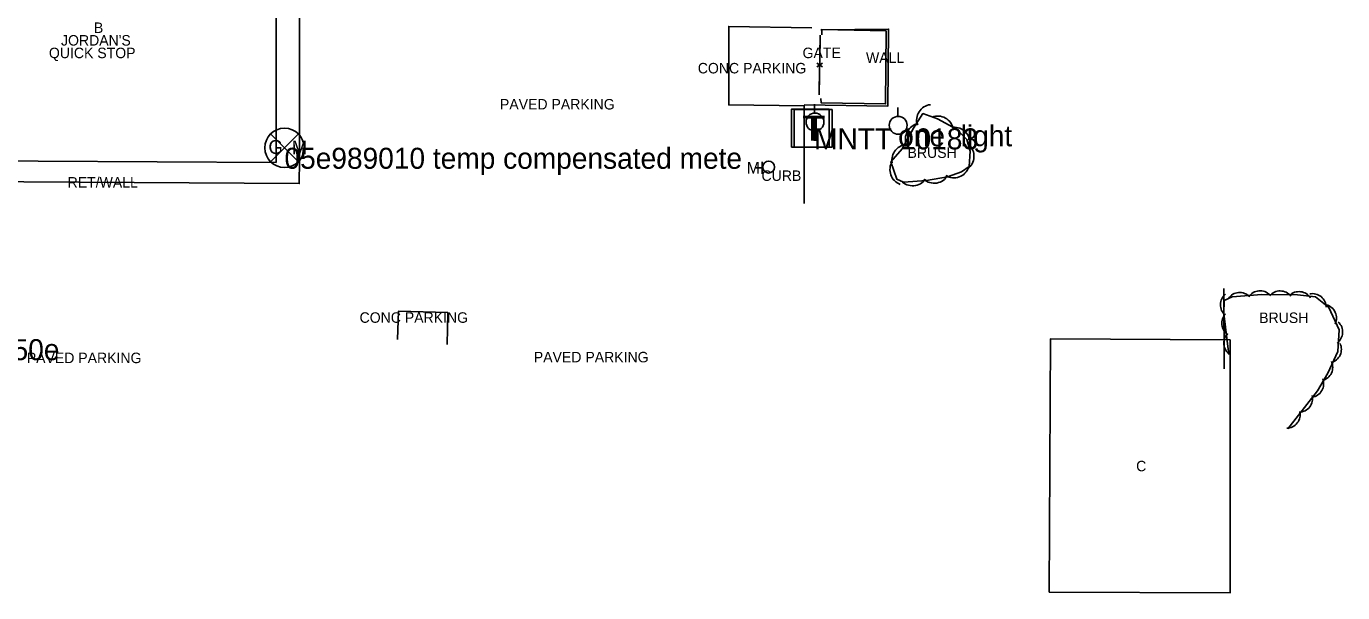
# Model space of a CAD drawing. Extents: x 1802180 to 1804859, y 572524 to 575172.
# Drawn here: x 1803724.4 to 1804037.7, y 573448 to 573582.9 of the extents above; entities that cross this region are included whole.
import ezdxf

# ---------------------------------------------------------------- set-up
doc = ezdxf.new("R2010")
doc.units = 0
for name, color, linetype in [('S_BUILDING', 7, 'Continuous'), ('S_BUILDING_ANNOT', 7, 'Continuous'), ('S_CURB_ANNOT', 7, 'Continuous'), ('S_FENCE', 7, 'Continuous'), ('S_GAS_UTILITIES', 7, 'Continuous'), ('S_GAS_UTILITIES_ANNOT', 7, 'Continuous'), ('S_GATE_ANNOT', 7, 'Continuous'), ('S_MANHOLE', 7, 'Continuous'), ('S_PARKING', 7, 'Continuous'), ('S_PARKING_ANNOT', 7, 'Continuous'), ('S_TELEPHONE_UTILITIES', 7, 'Continuous'), ('S_TELEPHONE_UTILITIES_ANNOT', 7, 'Continuous'), ('S_TREE', 7, 'Continuous'), ('S_TREE_ANNOT', 7, 'Continuous'), ('S_UTILITY_POLE', 7, 'Continuous'), ('S_UTILITY_POLE_ANNOT', 7, 'Continuous'), ('S_WALL', 7, 'Continuous'), ('S_WALL_ANNOT', 7, 'Continuous')]:
    doc.layers.add(name, color=color, linetype=linetype)

msp = doc.modelspace()

# ---------------------------------------------------------------- linework, layer by layer
at = {"layer": 'S_BUILDING'}
for points in [[(1803783.86, 573550.47), (1803698.78, 573550.9), (1803698.98, 573602.8), (1803708.84, 573602.75), (1803708.79, 573606.66), (1803731.22, 573606.3), (1803738.28, 573609.94), (1803743.5, 573610.3), (1803750.85, 573606.56), (1803771.09, 573606.24), (1803771.14, 573602.45), (1803783.83, 573602.26), (1803783.86, 573550.47)], [(1803967.81, 573448.14), (1803968.13, 573508.42), (1804010.87, 573508.2), (1804010.92, 573447.98), (1803967.81, 573448.14)]]:
    msp.add_lwpolyline(points, dxfattribs=at)
at = {"layer": 'S_FENCE'}
for p, q in [((1803913.28, 573580.77), (1803913.12, 573566.53)), ((1803913.87, 573574.1), (1803912.53, 573573.19)), ((1803912.54, 573574.12), (1803913.86, 573573.18))]:
    msp.add_line(p, q, dxfattribs=at)
for points in [[(1803913.28, 573580.77), (1803913.21, 573574.29)], [(1803913.19, 573573), (1803913.12, 573566.53)]]:
    msp.add_lwpolyline(points, dxfattribs=at)
at = {"layer": 'S_GAS_UTILITIES'}
for p, q in [((1803782.5, 573550.63), (1803789.12, 573557.25)), ((1803782.5, 573557.25), (1803789.12, 573550.63))]:
    msp.add_line(p, q, dxfattribs=at)
msp.add_circle((1803785.81, 573553.94), 4.68, dxfattribs=at)
at = {"layer": 'S_MANHOLE'}
for p, q in [((1803899.48, 573547.73), (1803899.48, 573550.57)), ((1803897.9, 573549.13), (1803899.48, 573549.13))]:
    msp.add_line(p, q, dxfattribs=at)
msp.add_circle((1803901.06, 573549.35), 1.42, dxfattribs=at)
at = {"layer": 'S_PARKING'}
msp.add_line((1804009.42, 573520.45), (1804009.47, 573501.32), dxfattribs=at)
for points in [[(1803789.37, 573551.02), (1803789.36, 573601.75), (1803840.12, 573602.03)], [(1803911.36, 573582.54), (1803891.57, 573582.86), (1803891.55, 573564.14), (1803909.51, 573563.94), (1803909.52, 573540.67)], [(1803909.54, 573564.15), (1803929.4, 573563.83), (1803929.6, 573582.22), (1803913.5, 573582.06)], [(1803812.68, 573508.27), (1803812.98, 573515.06), (1803824.67, 573514.69), (1803824.54, 573507.1)]]:
    msp.add_lwpolyline(points, dxfattribs=at)
at = {"layer": 'S_TELEPHONE_UTILITIES'}
for points in [[(1803906.47, 573554.11), (1803906.47, 573563.11), (1803915.47, 573563.11), (1803915.47, 573554.11)], [(1803907.15, 573554.05), (1803907.15, 573563.05), (1803916.15, 573563.05), (1803916.15, 573554.05)]]:
    msp.add_lwpolyline(points, close=True, dxfattribs=at)
at = {"layer": 'S_TREE'}
for points in [[(1803930.16, 573550.57), (1803932.87, 573553.69), (1803935.56, 573558.6), (1803937.78, 573562.09), (1803941.27, 573560.87), (1803945.8, 573558.39), (1803948.23, 573555.92), (1803949, 573553.13), (1803948.78, 573549.51), (1803946.97, 573548.19), (1803943.66, 573547), (1803938.64, 573546.17), (1803933.16, 573545.76), (1803931.6, 573546.44), (1803930.16, 573550.57)], [(1804010.56, 573504.67), (1804009.43, 573514.49), (1804009.48, 573517.59), (1804011.4, 573518.43), (1804018.43, 573519.03), (1804026.91, 573518.94), (1804031.23, 573518.45), (1804034.41, 573515.88), (1804036.82, 573510.62), (1804036.51, 573505.42), (1804034.13, 573500.3), (1804031.67, 573496.04), (1804024.63, 573486.97)]]:
    msp.add_lwpolyline(points, dxfattribs=at)
for centre, radius, start, end in [((1803939.99, 573560.51), 3.72, 96.793, 198.3899), ((1803937.33, 573556.03), 3.72, 100.468, 202.0649), ((1803941.35, 573557.77), 3.72, 10.428, 112.0249), ((1803945.26, 573555.11), 3.72, 353.7499, 95.3468), ((1803934.1, 573550.97), 3.72, 88.2809, 189.8778), ((1803946.21, 573551.94), 3.72, 305.7428, 47.3397), ((1803933.65, 573548.73), 3.72, 148.4197, 250.0166), ((1803935.32, 573548.61), 3.72, 223.5144, 325.1113), ((1803940.45, 573549.22), 3.72, 228.5093, 330.1062), ((1803945.15, 573550.5), 3.72, 239.0593, 340.6562), ((1804011.83, 573516.53), 3.24, 128.2838, 229.8807), ((1804013.19, 573516.24), 3.24, 44.0414, 145.6384), ((1804018.01, 573516.64), 3.24, 44.0414, 145.6384), ((1804022.81, 573516.61), 3.24, 38.6253, 140.2222), ((1804027.31, 573516.45), 3.24, 32.7141, 134.311), ((1804030.54, 573515.96), 3.24, 0.3693, 101.9662), ((1804032.98, 573513.4), 3.24, 333.8313, 75.4282), ((1804012.14, 573512.16), 3.24, 135.7646, 237.3615), ((1804034.45, 573510.05), 3.24, 305.7679, 47.3648), ((1804012.62, 573507.44), 3.24, 135.7646, 237.3615), ((1804034.14, 573505.94), 3.24, 284.244, 25.8409), ((1804032.08, 573501.66), 3.24, 284.244, 25.8409), ((1804029.92, 573497.73), 3.24, 279.2136, 20.8105), ((1804027.29, 573494.21), 3.24, 271.3803, 12.9772), ((1804024.32, 573490.39), 3.24, 271.3803, 12.9772)]:
    msp.add_arc(centre, radius, start, end, dxfattribs=at)
at = {"layer": 'S_UTILITY_POLE'}
for p, q in [((1803911.96, 573562.21), (1803911.96, 573564.32)), ((1803931.77, 573561.44), (1803931.77, 573563.54))]:
    msp.add_line(p, q, dxfattribs=at)
for centre in [(1803912.08, 573560.07), (1803931.89, 573559.29)]:
    msp.add_circle(centre, 2.13, dxfattribs=at)
at = {"layer": 'S_WALL'}
for points in [[(1803913.69, 573580.84), (1803913.68, 573582.08), (1803929.02, 573581.79), (1803928.88, 573564.39), (1803913.58, 573564.61), (1803913.51, 573565.64)], [(1803789.36, 573551.02), (1803789.31, 573545.42), (1803697.53, 573546.02), (1803695.38, 573551), (1803702.79, 573550.87)]]:
    msp.add_lwpolyline(points, dxfattribs=at)

# ---------------------------------------------------------------- texts
at = {"layer": 'S_BUILDING_ANNOT'}
for s, p in [("JORDAN'S", (1803732.62, 573578.28)), ('B', (1803740.45, 573581.28)), ('QUICK STOP', (1803729.74, 573575.28)), ('C', (1803988.53, 573476.89))]:
    msp.add_text(s, height=2.5, dxfattribs=at).set_placement(p)
at = {"layer": 'S_CURB_ANNOT'}
msp.add_text('CURB', height=2.5, dxfattribs=at).set_placement((1803899.36, 573546.05))
at = {"layer": 'S_GAS_UTILITIES'}
for s, p in [('G', (1803781.99, 573552.48)), ('M', (1803787.55, 573552.37))]:
    msp.add_text(s, height=3.3, rotation=360, dxfattribs=at).set_placement(p)
at = {"layer": 'S_GAS_UTILITIES_ANNOT'}
msp.add_text('05e989010 temp compensated mete', height=5, dxfattribs=at).set_placement((1803785.81, 573548.94))
at = {"layer": 'S_GATE_ANNOT'}
msp.add_text('GATE', height=2.5, dxfattribs=at).set_placement((1803909.13, 573575.29))
at = {"layer": 'S_MANHOLE'}
msp.add_text('M', height=2.82, dxfattribs=at).set_placement((1803895.82, 573547.77))
at = {"layer": 'S_PARKING_ANNOT'}
for s, p in [('CONC PARKING', (1803884.19, 573571.65)), ('PAVED PARKING', (1803837.1, 573563.06)), ('CONC PARKING', (1803803.69, 573512.26)), ('PAVED PARKING', (1803724.47, 573502.65)), ('PAVED PARKING', (1803845.17, 573502.84)), ('PAVED PARKING', (1803845.17, 573502.84))]:
    msp.add_text(s, height=2.5, dxfattribs=at).set_placement(p)
at = {"layer": 'S_TELEPHONE_UTILITIES'}
for p in [(1803909.04, 573555.61), (1803909.71, 573555.55)]:
    msp.add_text('T', height=6, rotation=360, dxfattribs=at).set_placement(p)
at = {"layer": 'S_TELEPHONE_UTILITIES_ANNOT'}
msp.add_text('MNTT 10183 ', height=5, dxfattribs=at).set_placement((1803911.88, 573553.56))
at = {"layer": 'S_TREE_ANNOT'}
for p in [(1803934.12, 573551.53), (1804017.82, 573512.21)]:
    msp.add_text('BRUSH', height=2.5, dxfattribs=at).set_placement(p)
at = {"layer": 'S_UTILITY_POLE_ANNOT'}
for s, p in [('one  light', (1803931.89, 573554.29)), ('11126w 50e', (1803695.82, 573503.36))]:
    msp.add_text(s, height=5, dxfattribs=at).set_placement(p)
at = {"layer": 'S_WALL_ANNOT'}
for s, p in [('WALL', (1803924.23, 573574.15)), ('RET/WALL', (1803734.19, 573544.45))]:
    msp.add_text(s, height=2.5, dxfattribs=at).set_placement(p)

doc.saveas('drawing.dxf')
